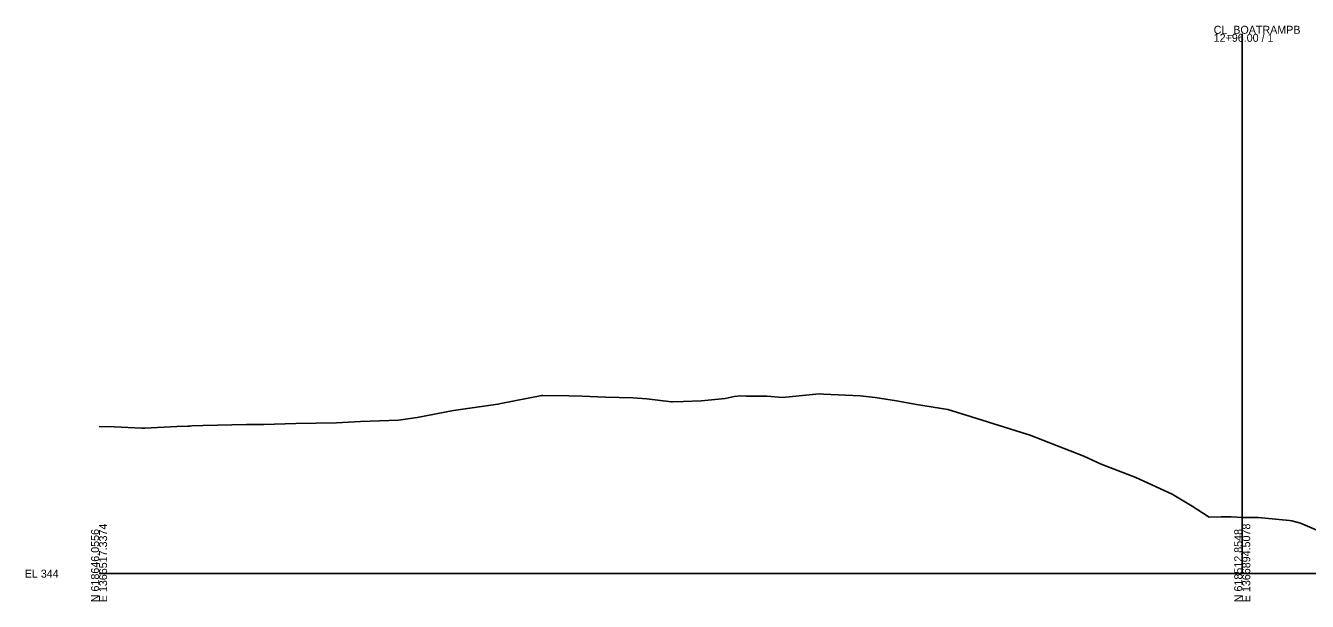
# Model space of a CAD drawing. Extents: x -26 to 803, y -24 to 3192.
# Drawn here: x -25.7 to 422.8, y 2990.3 to 3191.6 of the extents above; entities that cross this region are included whole.
import ezdxf

# ---------------------------------------------------------------- set-up
doc = ezdxf.new("R2010")
doc.units = 0
doc.layers.add('DESIGN - SHEET - Light Grid', color=7, linetype='Continuous')
doc.layers.add('SURVEY - GROUND - Top of Ground', color=7, linetype='Continuous')

msp = doc.modelspace()

# ---------------------------------------------------------------- linework, layer by layer
at = {"layer": 'DESIGN - SHEET - Light Grid'}
for p, q in [((400, 3000), (400, 3188.77)), ((0, 3000), (400, 3000)), ((400, 3000), (800, 3000))]:
    msp.add_line(p, q, dxfattribs=at)
at = {"layer": 'SURVEY - GROUND - Top of Ground'}
msp.add_lwpolyline([(0, 3051.42), (5.3, 3051.33), (14.98, 3050.92), (15.96, 3050.92), (27.24, 3051.41), (31.02, 3051.58), (31.78, 3051.62), (32.51, 3051.66), (36.34, 3051.77), (51.62, 3052.09), (57.6, 3052.2), (68.8, 3052.49), (83.09, 3052.77), (91.48, 3053.17), (104.77, 3053.61), (111.35, 3054.62), (123.99, 3057), (139.56, 3059.25), (140.58, 3059.53), (154.87, 3062.25), (155.33, 3062.33), (164.41, 3062.14), (169.08, 3062.06), (177.25, 3061.68), (186.77, 3061.45), (191.7, 3061.08), (200.31, 3060.12), (200.67, 3060.1), (204.47, 3060.19), (210.68, 3060.41), (213.14, 3060.63), (219.08, 3061.25), (222.2, 3061.93), (224.39, 3062.21), (226.42, 3062.09), (233.65, 3062), (239.09, 3061.64), (250.82, 3062.75), (252.34, 3062.92), (253.49, 3062.76), (266.34, 3062.13), (271.53, 3061.63), (279.02, 3060.46), (286.01, 3059.15), (297, 3057.35), (305.23, 3054.88), (324.57, 3048.81), (325.41, 3048.53), (344.61, 3041.03), (350.59, 3038.28), (362.77, 3033.66), (375.49, 3027.79), (382.43, 3023.56), (388.38, 3019.74), (392.59, 3019.81), (396.08, 3019.85), (398.06, 3019.69), (400, 3019.67), (405.52, 3019.59), (416.57, 3018.56), (417.36, 3018.44), (420.36, 3017.61), (427.71, 3014.55)], dxfattribs=at)

# ---------------------------------------------------------------- texts
at = {"layer": 'DESIGN - SHEET - Light Grid'}
for s, p in [('CL_BOATRAMPB', (390, 3188.77)), ('12+96.00 / 1', (390, 3185.97)), ('EL 344', (-26, 2998.6))]:
    msp.add_text(s, height=2.8, dxfattribs=at).set_placement(p)
for s, p in [('N 618646.0556', (0, 2990)), ('E 1366517.3374', (2.8, 2990)), ('N 618512.8548', (400, 2990)), ('E 1366894.5078', (402.8, 2990))]:
    msp.add_text(s, height=2.8, rotation=90, dxfattribs=at).set_placement(p)

doc.saveas('drawing.dxf')
